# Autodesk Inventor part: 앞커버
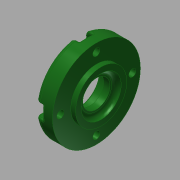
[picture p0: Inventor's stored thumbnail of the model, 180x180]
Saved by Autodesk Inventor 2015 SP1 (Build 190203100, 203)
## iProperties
Created: 2015-11
Part Number: 앞커버
Material: 알루미늄 6061
Document SubType Name: Modeling
Designer: mduedu
Density: 1 g/cm^3
Appearance: 매끄러움 - 짙은 산림 녹색
Author: mduedu
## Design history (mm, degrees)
sketch "스케치1"
  geometry: L1 (-7, 0)-(7, 0); L2 (-7, 0)-(-7, 27.5); L3 (-7, 27.5)-(4, 27.5); L4 (4, 27.5)-(4, 16); L5 (4, 16)-(7, 16); L6 (7, 16)-(7, 0); 2 further points
  constraints: 12 end point, 3 perpendicular, 2 parallel, 1 coincident, 1 horizontal, 1 midpoint
  dimensions: "d0" = 14 distance of L1.start L1.end; "d1" = 55 diameter of L3 L1; "d2" = 3 distance of L4.end L5.end; "d3" = 32 diameter of L5 L1
revolve "회전1" sketch "스케치1" stored, may be unused: angle "d4" = 90 deg
hole "구멍1" diameter "d7" = 25; stored, may be unused: countersink angle "d11" = 90 deg, drill point angle "d13" = 0 deg; dims "d5" = 10, "d6" = 10, "d8" = 6, "d9" = 4, "d10" = 2, "d12" = 3
hole "구멍2" diameter "d16" = 25; stored, may be unused: countersink angle "d20" = 90 deg, drill point angle "d22" = 0 deg; dims "d17" = 6, "d18" = 4, "d19" = 2, "d21" = 7, "d63" = 10, "d64" = 10
hole "구멍3" diameter "d25" = 17; stored, may be unused: countersink angle "d29" = 90 deg, drill point angle "d31" = 0 deg; dims "d23" = 10, "d24" = 10, "d26" = 6, "d27" = 4, "d28" = 2, "d30" = 4.2
chamfer "모따기1" distance "d32" = 0.6; stored, may be unused: second distance "d33" = 2, angle "d34" = 30 deg
fillet "모깎기1" dims "d35" = 0.3
fillet "모깎기2" dims "d36" = 3
fillet "모깎기3" dims "d37" = 3
sketch "스케치2" dims "d39" = 45
  geometry: C1 r 12.846 at (0, 0) reference; C2 r 24.5 at (0, 0) reference; 6 further points
  constraints: 2 vertical alignment, 1 coincident, 7 other
  dimensions: "d42" = 360 deg dimension on point (0, 0) point (0, 22.5) (derived)
sketch "스케치3"
  geometry: 8 further points
  constraints: 4 coincident
hole "구멍4" sketch "스케치3" at (-22.5, 0), (0, -22.5), (22.5, 0), (0, 22.5) diameter "d44" = 4.5; stored, may be unused: countersink angle "d48" = 90 deg, drill point angle "d50" = 0 deg; dims "d45" = 6, "d46" = 8, "d47" = 4.6, "d49" = 8
sketch "스케치4"
  geometry: L1 (-4, 0)-(-4, -4.708); L2 (4, 0)-(4, -4.708); A1 r 4 centre (0, 0) between (-4, 0) and (4, 0) reference; A2 r 27.5 centre (0, 22.5) between (-4, -4.708) and (4, -4.708) reference; 3 further points
  constraints: 4 end point, 4 point on circle, 2 tangent, 1 parallel, 1 vertical
extrude "돌출1" cut sketch "스케치4" stored distance "d51" = 0; taper "d52" = 0 deg
fillet "모깎기5" dims "d56" = 0.3
fillet "모깎기6" dims "d57" = 1
node "솔리드1"
pattern_circular "원형 패턴1" dims angle "d54" = 360 deg
